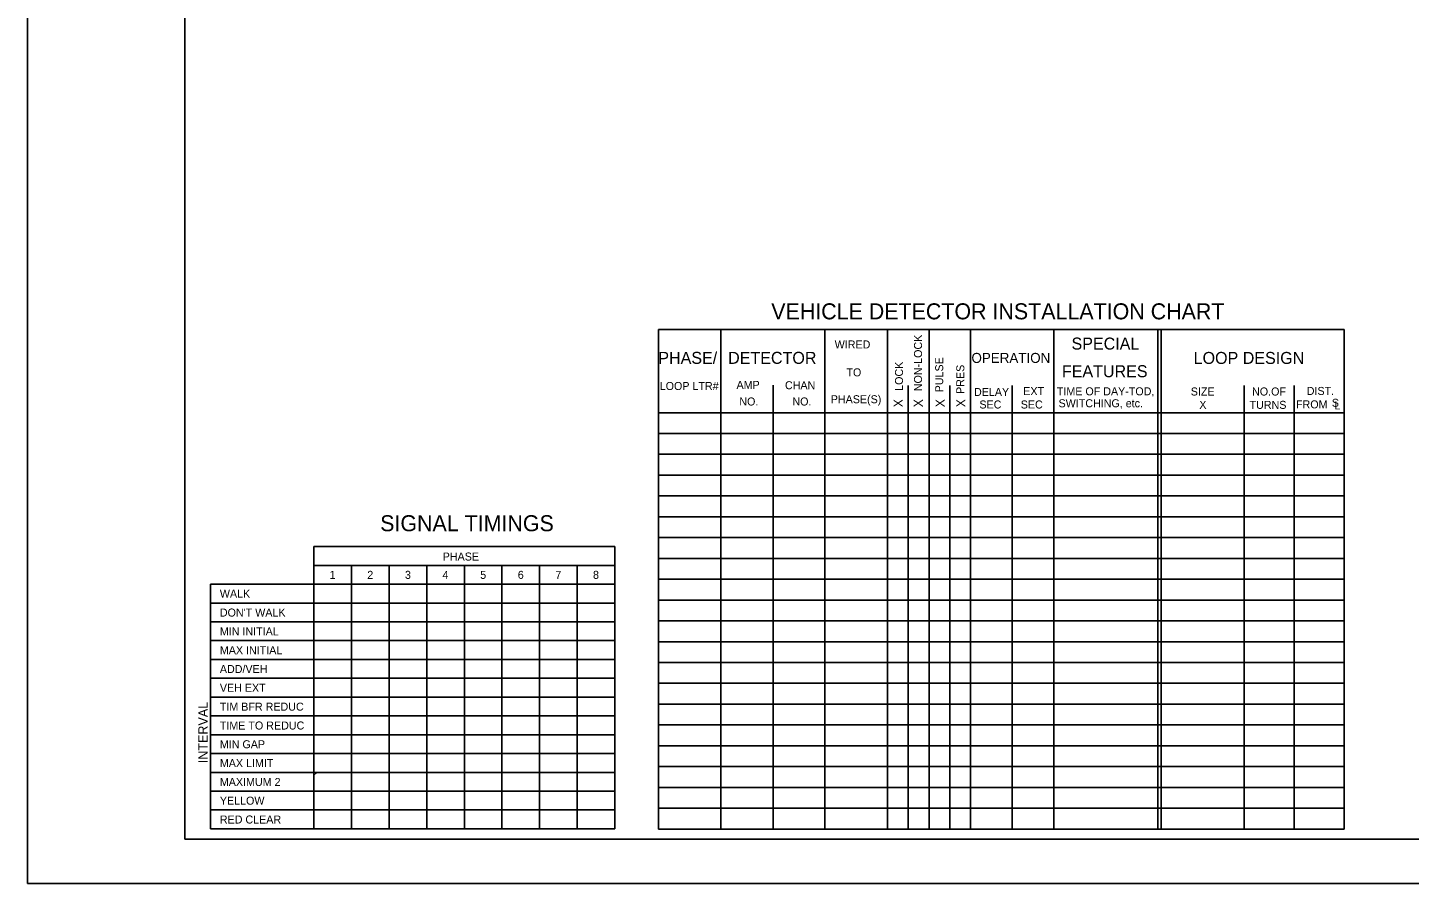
# Model space of a CAD drawing. Extents: x 0 to 3.01, y -0.05 to 1.83.
# Drawn here: x 0 to 1.481, y 0 to 0.917 of the extents above; entities that cross this region are included whole.
import ezdxf

# ---------------------------------------------------------------- set-up
doc = ezdxf.new("R2010")
doc.units = 0
for name, color, linetype in [('RD_SHT_IplotShp', 7, 'Continuous'), ('TR_TS_Border', 7, 'Continuous'), ('TR_TS_Loop Detector Chart', 7, 'Continuous'), ('TR_TS_Phase1', 7, 'Continuous'), ('TR_TS_Phase2', 7, 'Continuous'), ('TR_TS_Phase3', 7, 'Continuous'), ('TR_TS_Phase4', 7, 'Continuous'), ('TR_TS_Phase5', 7, 'Continuous'), ('TR_TS_Phase6', 7, 'Continuous'), ('TR_TS_Phase7', 7, 'Continuous'), ('TR_TS_Phase8', 7, 'Continuous')]:
    doc.layers.add(name, color=color, linetype=linetype)

msp = doc.modelspace()

# ---------------------------------------------------------------- linework, layer by layer
at = {"layer": 'RD_SHT_IplotShp'}
msp.add_lwpolyline([(0, 0), (3, 0), (3, 1.8333), (0, 1.8333)], close=True, dxfattribs=at)
at = {"layer": 'TR_TS_Border'}
for p, q in [((0, 0), (0, 1.8333)), ((0.1686, 1.7754), (0.1686, 0.0475)), ((0.3068, 0.3607), (0.6293, 0.3607)), ((0.3068, 0.3607), (0.3068, 0.3204)), ((0.6293, 0.3607), (0.6293, 0.0585)), ((0.3068, 0.3406), (0.6293, 0.3406)), ((0.3471, 0.3406), (0.3471, 0.0585)), ((0.3874, 0.3406), (0.3874, 0.0585)), ((0.4278, 0.3406), (0.4278, 0.0585)), ((0.4681, 0.3406), (0.4681, 0.0585)), ((0.5083, 0.3406), (0.5083, 0.0585)), ((0.5486, 0.3406), (0.5486, 0.0585)), ((0.589, 0.3406), (0.589, 0.0585)), ((0.1959, 0.3204), (0.1959, 0.0585)), ((0.1959, 0.3204), (0.3068, 0.3204)), ((0.3068, 0.3204), (0.3068, 0.1189)), ((0.3068, 0.3204), (0.6293, 0.3204)), ((0.1959, 0.3003), (0.6293, 0.3003)), ((0.1959, 0.2801), (0.6293, 0.2801)), ((0.1959, 0.26), (0.6293, 0.26)), ((0.1959, 0.2398), (0.6293, 0.2398)), ((0.1959, 0.2197), (0.6293, 0.2197)), ((0.1959, 0.1995), (0.6293, 0.1995)), ((0.1959, 0.1793), (0.6293, 0.1793)), ((0.1959, 0.1592), (0.6293, 0.1592)), ((0.1959, 0.139), (0.6293, 0.139)), ((0.1959, 0.1189), (0.3068, 0.1189)), ((0.3068, 0.0585), (0.3068, 0.1189)), ((0.3068, 0.1189), (0.6293, 0.1189)), ((0.3068, 0.116), (0.3099, 0.1189)), ((0.1959, 0.0987), (0.6293, 0.0987)), ((0.1959, 0.0786), (0.6293, 0.0786)), ((0.1686, 0.0475), (2.9623, 0.0475)), ((0.1959, 0.0585), (0.6293, 0.0585)), ((0.0238, 0), (3, 0))]:
    msp.add_line(p, q, dxfattribs=at)
at = {"layer": 'TR_TS_Loop Detector Chart'}
for p, q in [((0.6761, 0.5934), (1.4109, 0.5934)), ((0.6761, 0.0581), (0.6761, 0.5934)), ((0.743, 0.0581), (0.743, 0.5934)), ((0.8545, 0.0581), (0.8545, 0.5934)), ((0.9214, 0.0581), (0.9214, 0.5935)), ((0.966, 0.0581), (0.966, 0.5932)), ((1.0106, 0.0581), (1.0106, 0.5934)), ((1.0998, 0.0581), (1.0998, 0.5932)), ((1.2113, 0.0581), (1.2113, 0.5932)), ((1.2147, 0.0581), (1.2147, 0.5931)), ((1.4109, 0.5932), (1.4109, 0.0581)), ((0.7988, 0.0581), (0.7988, 0.5336)), ((0.9437, 0.0581), (0.9437, 0.5334)), ((0.9883, 0.0581), (0.9883, 0.5334)), ((1.0552, 0.0581), (1.0552, 0.5334)), ((1.3039, 0.0581), (1.3039, 0.5334)), ((1.3574, 0.0581), (1.3574, 0.5334)), ((0.6761, 0.5042), (1.4109, 0.5042)), ((0.6761, 0.4819), (1.4109, 0.4819)), ((0.6761, 0.4596), (1.4109, 0.4596)), ((0.6761, 0.4373), (1.4109, 0.4373)), ((0.6761, 0.415), (1.4109, 0.415)), ((0.6761, 0.3927), (1.4109, 0.3927)), ((0.6761, 0.3704), (1.4109, 0.3704)), ((0.6761, 0.3481), (1.4109, 0.3481)), ((0.6761, 0.3258), (1.4109, 0.3258)), ((0.6761, 0.3035), (1.4109, 0.3035)), ((0.6761, 0.2812), (1.4109, 0.2812)), ((0.6761, 0.2589), (1.4109, 0.2589)), ((0.6761, 0.2366), (1.4109, 0.2366)), ((0.6761, 0.2143), (1.4109, 0.2143)), ((0.6761, 0.192), (1.4109, 0.192)), ((0.6761, 0.1697), (1.4109, 0.1697)), ((0.6761, 0.1473), (1.4109, 0.1473)), ((0.6761, 0.125), (1.4109, 0.125)), ((0.6761, 0.1027), (1.4109, 0.1027)), ((0.6761, 0.0804), (1.4109, 0.0804)), ((0.6761, 0.0581), (1.4109, 0.0581))]:
    msp.add_line(p, q, dxfattribs=at)

# ---------------------------------------------------------------- texts
at = {"layer": 'TR_TS_Border'}
for s, height, p in [('SIGNAL TIMINGS', 0.017156, (0.3778, 0.3772)), ('MAX INITIAL', 0.008578, (0.206, 0.2455))]:
    msp.add_text(s, height=height, dxfattribs=at).set_placement(p)
for s, height, rotation, p in [('PHASE', 0.00858, 360, (0.4448, 0.3458)), ('WALK', 0.00858, 360, (0.206, 0.306)), ("DON'T WALK", 0.00858, 360, (0.206, 0.2858)), ('MIN INITIAL', 0.008578, 360, (0.206, 0.2656)), ('ADD/VEH', 0.00858, 360, (0.206, 0.2253)), ('VEH EXT', 0.00858, 360, (0.206, 0.2052)), ('INTERVAL', 0.01008, 90, (0.193, 0.1286)), ('TIM BFR REDUC', 0.008578, 360, (0.206, 0.185)), ('TIME TO REDUC', 0.008578, 360, (0.206, 0.1648)), ('MIN GAP', 0.00858, 360, (0.206, 0.1447)), ('MAX LIMIT', 0.00858, 360, (0.206, 0.1245)), ('MAXIMUM 2', 0.00858, 360, (0.206, 0.1043)), ('YELLOW', 0.00858, 360, (0.206, 0.0843)), ('RED CLEAR', 0.00858, 360, (0.206, 0.0641))]:
    msp.add_text(s, height=height, rotation=rotation, dxfattribs=at).set_placement(p)
at = {"layer": 'TR_TS_Loop Detector Chart'}
for s, height, p in [('VEHICLE DETECTOR INSTALLATION CHART', 0.017156, (0.7969, 0.6042)), ('WIRED', 0.00858, (0.8649, 0.573)), ('SPECIAL', 0.01287, (1.1187, 0.5718)), ('PHASE/', 0.01287, (0.6759, 0.5565)), ('DETECTOR', 0.01287, (0.7507, 0.5565)), ('OPERATION', 0.01072, (1.0115, 0.5575)), ('LOOP DESIGN', 0.012867, (1.2496, 0.5564)), ('TO', 0.00858, (0.8775, 0.5431)), ('FEATURES', 0.01287, (1.1084, 0.5422)), ('LOOP LTR#', 0.00858, (0.6774, 0.5285)), ('AMP', 0.00858, (0.7597, 0.5297)), ('CHAN', 0.00858, (0.8116, 0.5293)), ('NO.', 0.00858, (0.7627, 0.5119)), ('NO.', 0.00858, (0.8196, 0.5119)), ('PHASE(S)', 0.00858, (0.8607, 0.5143)), ('DELAY', 0.00858, (1.0142, 0.5221)), ('EXT', 0.00858, (1.067, 0.523)), ('TIME OF DAY-TOD,', 0.008578, (1.103, 0.5228)), ('SWITCHING, etc.', 0.008578, (1.1048, 0.51)), ('SIZE', 0.00858, (1.2465, 0.5226)), ('NO.OF', 0.00858, (1.3122, 0.5226)), ('DIST.', 0.00858, (1.3708, 0.5232)), ('S', 0.00858, (1.3977, 0.5105)), ('SEC', 0.00858, (1.02, 0.5087)), ('SEC', 0.00858, (1.0643, 0.5087)), ('   X   ', 0.00858, (1.2461, 0.5083)), ('TURNS', 0.00858, (1.3095, 0.5083)), ('FROM', 0.00858, (1.3593, 0.5088)), ('L', 0.00858, (1.4004, 0.5077))]:
    msp.add_text(s, height=height, dxfattribs=at).set_placement(p)
for s, height, p in [('NON-LOCK', 0.00858, (0.9585, 0.5272)), (' PULSE', 0.00858, (0.9812, 0.5228)), ('LOCK', 0.00858, (0.9381, 0.5276)), ('PRES', 0.00858, (1.0038, 0.5243)), ('X', 0.00972, (0.9379, 0.51)), ('X', 0.00981, (0.9595, 0.51)), ('X', 0.00981, (0.9828, 0.51)), ('X', 0.00981, (1.005, 0.51))]:
    msp.add_text(s, height=height, rotation=90, dxfattribs=at).set_placement(p)
at = {"layer": 'TR_TS_Phase1'}
msp.add_text('1', height=0.00858, rotation=360, dxfattribs=at).set_placement((0.3236, 0.3262))
at = {"layer": 'TR_TS_Phase2'}
msp.add_text('2', height=0.00858, rotation=360, dxfattribs=at).set_placement((0.364, 0.3262))
at = {"layer": 'TR_TS_Phase3'}
msp.add_text('3', height=0.00858, rotation=360, dxfattribs=at).set_placement((0.4044, 0.3262))
at = {"layer": 'TR_TS_Phase4'}
msp.add_text('4', height=0.00858, rotation=360, dxfattribs=at).set_placement((0.4446, 0.3262))
at = {"layer": 'TR_TS_Phase5'}
msp.add_text('5', height=0.00858, rotation=360, dxfattribs=at).set_placement((0.485, 0.3262))
at = {"layer": 'TR_TS_Phase6'}
msp.add_text('6', height=0.00858, rotation=360, dxfattribs=at).set_placement((0.5253, 0.3262))
at = {"layer": 'TR_TS_Phase7'}
msp.add_text('7', height=0.00858, rotation=360, dxfattribs=at).set_placement((0.5656, 0.3262))
at = {"layer": 'TR_TS_Phase8'}
msp.add_text('8', height=0.00858, rotation=360, dxfattribs=at).set_placement((0.6059, 0.3262))

doc.saveas('drawing.dxf')
